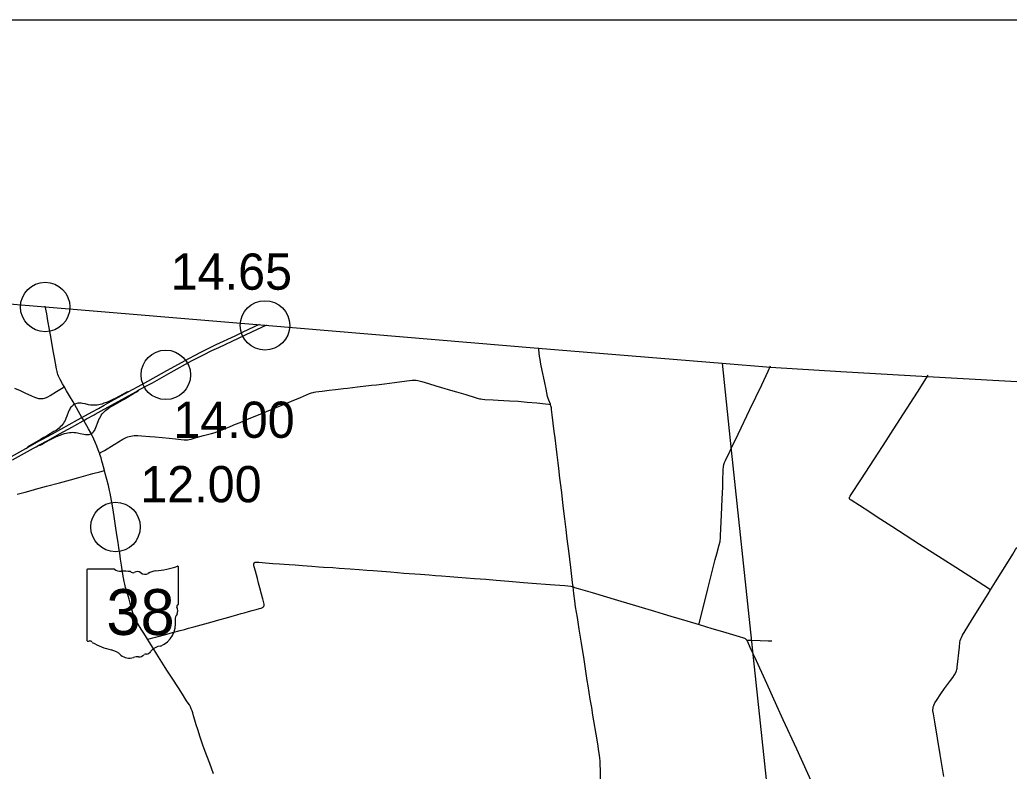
# Model space of a CAD drawing. Extents: x 1597222 to 1925846, y 496284 to 911751.
# Drawn here: x 1697422 to 1727439, y 608558 to 631367 of the extents above; entities that cross this region are included whole.
import ezdxf

# ---------------------------------------------------------------- set-up
doc = ezdxf.new("R2010")
doc.units = 0
for name, color, linetype in [('Default', 7, 'Continuous'), ('GM_X_County', 7, 'Continuous'), ('GM_X_County_Road', 7, 'Continuous'), ('GM_X_Interchange_Ramps', 7, 'Continuous'), ('GM_X_Interstate_Route', 7, 'Continuous'), ('GM_X_State_Route', 7, 'Continuous'), ('GM_X_State_Shield', 7, 'Continuous'), ('GM_X_Township', 7, 'Continuous'), ('GM_X_Township_Road', 7, 'Continuous'), ('SC_Scratch1', 7, 'Continuous')]:
    doc.layers.add(name, color=color, linetype=linetype)

msp = doc.modelspace()

# ---------------------------------------------------------------- linework, layer by layer
at = {"layer": 'Default'}
for centre in [(1698192, 622649), (1698192, 622649), (1704861, 622090), (1704861, 622090), (1704861, 622090), (1701852, 620589), (1701852, 620589), (1700327, 615972), (1700327, 615972)]:
    msp.add_circle(centre, 750, dxfattribs=at)
at = {"layer": 'GM_X_County'}
msp.add_lwpolyline([(1693117, 623083), (1698190, 622658), (1704859, 622098), (1713144, 621404), (1718727, 620944), (1720196, 620823), (1722331, 620688), (1724957, 620538), (1728386, 620349)], dxfattribs=at)
at = {"layer": 'GM_X_County_Road'}
for points in [[(1713520, 619692), (1713518, 619699), (1713468, 619821), (1713452, 619868), (1713435, 619932), (1713389, 620157), (1713340, 620398), (1713274, 620719), (1713233, 620912), (1713208, 621057), (1713194, 621155), (1713171, 621351), (1713162, 621414)], [(1714206, 614155), (1714191, 614282), (1714136, 614738), (1714107, 614999), (1714077, 615243), (1714041, 615536), (1714021, 615699), (1713998, 615895), (1713958, 616220), (1713931, 616448), (1713910, 616627), (1713889, 616807), (1713862, 617018), (1713827, 617311), (1713809, 617458), (1713773, 617751), (1713753, 617914), (1713725, 618158), (1713693, 618419), (1713660, 618679), (1713636, 618874), (1713607, 619119), (1713576, 619379), (1713557, 619542), (1713550, 619590), (1713543, 619622), (1713534, 619653), (1713520, 619692)], [(1697901, 617116), (1698234, 617207), (1698629, 617315), (1698962, 617405), (1699215, 617474), (1699500, 617552), (1699642, 617592), (1699848, 617647), (1699959, 617676), (1699989, 617684)], [(1697347, 616966), (1697585, 617029), (1697838, 617099), (1697901, 617116)], [(1726876, 614063), (1727027, 614309), (1727364, 614853), (1727545, 615146), (1727631, 615285), (1727661, 615324), (1727680, 615344), (1727695, 615358), (1727722, 615376), (1727749, 615388), (1727769, 615396), (1727790, 615402), (1727816, 615409), (1727880, 615419), (1728367, 615486), (1729717, 615669), (1730222, 615734), (1730681, 615801)], [(1701299, 612566), (1701339, 612576), (1701383, 612588), (1701457, 612607), (1701618, 612649), (1701815, 612701), (1702053, 612766), (1702290, 612830), (1702419, 612864), (1702544, 612897), (1702701, 612940), (1702812, 612970), (1703255, 613094), (1703460, 613152), (1703696, 613219), (1703870, 613266), (1704006, 613305), (1704138, 613342), (1704233, 613369), (1704359, 613406), (1704469, 613436), (1704593, 613468), (1704692, 613493), (1704740, 613506), (1704770, 613518), (1704785, 613525), (1704799, 613534), (1704811, 613544), (1704822, 613556), (1704830, 613570), (1704834, 613585), (1704837, 613601), (1704837, 613618), (1704835, 613634), (1704827, 613666), (1704813, 613714), (1704791, 613793), (1704783, 613824), (1704753, 613935), (1704703, 614126), (1704666, 614269), (1704629, 614411), (1704571, 614633), (1704536, 614760), (1704524, 614808), (1704522, 614825), (1704521, 614841), (1704523, 614857), (1704525, 614865), (1704529, 614874), (1704536, 614885), (1704542, 614891), (1704550, 614897), (1704563, 614902), (1704579, 614906), (1704595, 614908), (1704629, 614907), (1704678, 614903), (1704874, 614886), (1705103, 614868), (1705299, 614852), (1705438, 614843), (1705593, 614832), (1705773, 614818), (1706002, 614802), (1706280, 614781), (1706493, 614766), (1706640, 614757), (1706918, 614739), (1707114, 614726), (1707441, 614701), (1707719, 614681), (1707948, 614665), (1708144, 614651), (1708406, 614630), (1708667, 614608), (1708880, 614591), (1709076, 614574), (1709239, 614561), (1709583, 614537), (1709844, 614519), (1710029, 614503), (1710220, 614486), (1710465, 614469), (1710710, 614450), (1711217, 614413), (1711560, 614385), (1711871, 614360), (1712263, 614327), (1712704, 614291), (1713096, 614260), (1713374, 614236), (1713652, 614215), (1713962, 614191), (1714142, 614173), (1714206, 614155)], [(1715040, 608246), (1715036, 608574), (1715032, 608787), (1715028, 608869), (1715021, 608950), (1715009, 609048), (1714991, 609161), (1714954, 609388), (1714907, 609679), (1714839, 610083), (1714811, 610262), (1714774, 610488), (1714731, 610747), (1714666, 611152), (1714640, 611314), (1714541, 611946), (1714461, 612448), (1714393, 612870), (1714338, 613226), (1714285, 613550), (1714259, 613729), (1714229, 613956), (1714206, 614155)], [(1714206, 614155), (1714246, 614138), (1714358, 614107), (1714783, 613982), (1715560, 613748), (1716204, 613555), (1716674, 613416), (1716940, 613336), (1717176, 613265), (1717662, 613120), (1718030, 613009)], [(1725457, 608403), (1725348, 609067), (1725182, 610054), (1725139, 610296), (1725126, 610393), (1725124, 610420), (1725125, 610440), (1725128, 610466), (1725131, 610489), (1725137, 610511), (1725143, 610534), (1725152, 610558), (1725160, 610580), (1725187, 610637), (1725229, 610707), (1725367, 610911), (1725480, 611072), (1725627, 611269), (1725724, 611402), (1725777, 611485), (1725817, 611557), (1725837, 611603), (1725851, 611650), (1725858, 611680), (1725863, 611715), (1725927, 612319), (1725943, 612466), (1725955, 612530), (1725968, 612576), (1725987, 612621), (1726025, 612693), (1726380, 613262), (1726803, 613946), (1726876, 614063)], [(1718030, 613009), (1718414, 612894), (1718743, 612795), (1719242, 612647), (1719380, 612604), (1719405, 612593), (1719424, 612584), (1719439, 612575), (1719450, 612565), (1719460, 612555), (1719471, 612542), (1719475, 612536)], [(1719475, 612536), (1719479, 612529), (1719489, 612510), (1719499, 612491), (1719574, 612327), (1719664, 612128)], [(1719664, 612128), (1719709, 612028), (1720072, 611236), (1720382, 610549), (1720574, 610132), (1720984, 609237), (1721514, 608073), (1722019, 606916), (1722233, 606423), (1722246, 606395), (1722256, 606375), (1722265, 606360), (1722278, 606348), (1722291, 606338), (1722301, 606333)]]:
    msp.add_lwpolyline(points, dxfattribs=at)
at = {"layer": 'GM_X_Interchange_Ramps'}
for points in [[(1700714, 620072), (1700698, 620072), (1700685, 620068), (1700660, 620060), (1700649, 620054), (1700538, 619994), (1700335, 619886), (1700246, 619842), (1700142, 619794), (1700051, 619755), (1699974, 619725), (1699912, 619704), (1699864, 619691), (1699816, 619680), (1699767, 619672), (1699718, 619667), (1699669, 619666), (1699619, 619668), (1699570, 619673), (1699505, 619684), (1699409, 619705), (1699328, 619722), (1699279, 619730), (1699247, 619732), (1699214, 619730), (1699181, 619725), (1699149, 619717), (1699079, 619699)], [(1699588, 618804), (1699610, 618820), (1699636, 618839), (1699648, 618850), (1699659, 618862), (1699680, 618887), (1699697, 618915), (1699712, 618944), (1699732, 618989), (1699799, 619173), (1699824, 619233), (1699846, 619278), (1699869, 619320), (1699895, 619362), (1699924, 619402), (1699956, 619439), (1699989, 619475), (1700025, 619508), (1700063, 619539), (1700103, 619568), (1700158, 619604), (1700256, 619662), (1700587, 619852), (1700875, 620019), (1700969, 620071), (1700992, 620085), (1701011, 620100), (1701024, 620110), (1701032, 620119), (1701038, 620130)], [(1699079, 619699), (1699046, 619673), (1699020, 619652), (1698996, 619630), (1698975, 619605), (1698955, 619579), (1698938, 619551), (1698923, 619522), (1698904, 619477), (1698853, 619339), (1698822, 619263), (1698794, 619204), (1698770, 619161), (1698744, 619119), (1698716, 619080), (1698684, 619042), (1698650, 619007), (1698614, 618974), (1698575, 618943), (1698522, 618905), (1698457, 618866), (1698258, 618748), (1698154, 618687), (1698050, 618628), (1697692, 618424), (1697679, 618414), (1697666, 618400), (1697654, 618384)], [(1698004, 618454), (1698020, 618454), (1698029, 618456), (1698038, 618458), (1698060, 618467), (1698076, 618475), (1698163, 618524), (1698377, 618637), (1698450, 618674), (1698540, 618715), (1698645, 618759), (1698721, 618789), (1698783, 618809), (1698830, 618822), (1698878, 618833), (1698927, 618840), (1698976, 618844), (1699025, 618845), (1699074, 618843), (1699122, 618838), (1699171, 618830), (1699251, 618813), (1699362, 618788), (1699411, 618779), (1699443, 618776), (1699476, 618775), (1699492, 618775), (1699508, 618777), (1699524, 618780), (1699588, 618804)]]:
    msp.add_lwpolyline(points, dxfattribs=at)
at = {"layer": 'GM_X_Interstate_Route'}
for points in [[(1697076, 618065), (1697608, 618358), (1697654, 618384), (1698031, 618593), (1698109, 618637), (1698411, 618803), (1699173, 619222), (1699309, 619297), (1699618, 619468), (1699805, 619571), (1699977, 619666), (1700192, 619786), (1700508, 619960), (1700714, 620072), (1701015, 620240), (1701212, 620349), (1701557, 620540), (1701888, 620722), (1702232, 620911), (1702549, 621085), (1702739, 621185), (1702915, 621276), (1703161, 621399), (1703383, 621506), (1703961, 621778), (1704199, 621891), (1704694, 622125)], [(1702015, 620667), (1702636, 621011), (1702810, 621104), (1703000, 621201), (1703249, 621325), (1703457, 621424), (1704457, 621892), (1704913, 622107)], [(1699704, 619392), (1699893, 619497), (1700941, 620075), (1701038, 620130), (1701444, 620352), (1702015, 620667)], [(1699348, 619195), (1699363, 619203), (1699448, 619251), (1699678, 619378), (1699704, 619392)], [(1697921, 618407), (1698004, 618454), (1698271, 618600), (1698629, 618799), (1699021, 619013)], [(1699021, 619013), (1699090, 619051), (1699348, 619195)], [(1697205, 618011), (1697839, 618362), (1697921, 618407)]]:
    msp.add_lwpolyline(points, dxfattribs=at)
at = {"layer": 'GM_X_State_Route'}
for points in [[(1698770, 620234), (1698720, 620320), (1698647, 620448), (1698617, 620506), (1698598, 620551), (1698580, 620597), (1698566, 620643), (1698555, 620691), (1698539, 620771), (1698478, 621111), (1698448, 621272), (1698405, 621497), (1698372, 621691), (1698322, 621966), (1698277, 622224), (1698239, 622446), (1698195, 622672)], [(1699851, 618174), (1699846, 618191), (1699840, 618209), (1699803, 618316), (1699763, 618423), (1699713, 618545), (1699673, 618635), (1699631, 618724), (1699588, 618804), (1699577, 618826), (1699505, 618955), (1699363, 619203), (1699334, 619254), (1699309, 619297), (1699203, 619481), (1699079, 619699), (1699041, 619766), (1698934, 619951), (1698843, 620107), (1698770, 620234)], [(1699931, 617905), (1699913, 617972), (1699886, 618066), (1699851, 618174)], [(1703297, 608484), (1703183, 608792), (1703098, 609023), (1702990, 609315), (1702934, 609469), (1702892, 609593), (1702820, 609828), (1702776, 609970), (1702733, 610111), (1702697, 610237), (1702669, 610329), (1702649, 610393), (1702624, 610456), (1702598, 610513), (1702568, 610572), (1702531, 610628), (1702484, 610697), (1702386, 610849), (1702253, 611056), (1702022, 611414), (1701906, 611593), (1701836, 611704), (1701732, 611871), (1701584, 612108), (1701471, 612289), (1701351, 612484), (1701299, 612566), (1701263, 612622), (1701186, 612748), (1701107, 612873), (1700995, 613055), (1700954, 613125), (1700924, 613183), (1700904, 613228), (1700887, 613274), (1700856, 613367), (1700782, 613619), (1700738, 613777), (1700705, 613887), (1700665, 614012), (1700630, 614138), (1700606, 614233), (1700590, 614313), (1700551, 614540), (1700510, 614815), (1700482, 614994), (1700456, 615172), (1700430, 615334), (1700404, 615496), (1700379, 615675), (1700340, 615934), (1700285, 616291), (1700245, 616550), (1700206, 616777), (1700164, 617003), (1700146, 617083), (1700109, 617226), (1700014, 617591), (1699989, 617684), (1699931, 617905)]]:
    msp.add_lwpolyline(points, dxfattribs=at)
at = {"layer": 'GM_X_State_Shield'}
for p, q in [((1699453, 614658), (1699453, 612545)), ((1700296, 614695), (1699481, 614695)), ((1702237, 613641), (1702237, 614747)), ((1702237, 613642), (1702237, 613641))]:
    msp.add_line(p, q, dxfattribs=at)
for centre, radius, start, end in [((1701246, 617576), 2953, 275.8445, 288.9065), ((1702207, 614752), 31, 351.8621, 97.738), ((1699485, 614663), 32.3, 98.1301, 188.1301), ((1700490, 614940), 313, 231.6195, 271.1119), ((1700594, 613508), 1123, 80.4867, 94.9883), ((1700849, 614674), 90.3, 219.7921, 297.1024), ((1700981, 614429), 188, 54.4667, 119.1411), ((1701224, 614764), 226, 233.8562, 294.8282), ((1701622, 614049), 594, 97.3462, 120.7689), ((1702230, 613560), 48, 107.944, 210.337), ((1702204, 613637), 33.2, 289.6038, 7.7341), ((1702349, 613179), 210, 136.8065, 186.9296), ((1701925, 613421), 288, 340.033, 23.6496), ((1701411, 613038), 739, 292.3089, 8.9858), ((1699485, 612540), 32.5, 171.9584, 258.3066), ((1699490, 612757), 248, 267.339, 280.6039), ((1699541, 612423), 89.5, 29.7484, 93.2717), ((1700672, 614322), 2132, 240.4129, 257.1985), ((1701722, 611952), 404, 94.4031, 142.5768), ((1700036, 611596), 667, 47.1842, 75.836), ((1700757, 612413), 423, 230.7004, 286.2918), ((1701033, 612254), 226, 268.777, 315.5493), ((1701237, 612050), 63.5, 65.7517, 132.6484), ((1701210, 612340), 239, 282.8732, 323.2771), ((1701002, 611682), 348, 85.6951, 111.2099)]:
    msp.add_arc(centre, radius, start, end, dxfattribs=at)
at = {"layer": 'GM_X_Township'}
msp.add_lwpolyline([(1718727, 620944), (1719007, 618308), (1719624, 612493), (1719675, 612012), (1720412, 605075), (1720984, 599696), (1721634, 593580), (1721696, 592990)], dxfattribs=at)
at = {"layer": 'GM_X_Township_Road'}
for points in [[(1719006, 618352), (1719216, 618793), (1719569, 619534), (1719930, 620286), (1720126, 620705), (1720198, 620859)], [(1722649, 616960), (1722942, 617405), (1723351, 618036), (1723706, 618587), (1723916, 618917), (1724653, 620061), (1724983, 620576)], [(1697266, 620187), (1697430, 620111), (1697595, 620038), (1697759, 619962), (1697781, 619952)], [(1697781, 619952), (1697864, 619914), (1697925, 619890), (1697956, 619881), (1697988, 619874), (1698037, 619869), (1698070, 619868), (1698103, 619869), (1698135, 619873), (1698168, 619880), (1698199, 619890), (1698229, 619903), (1698273, 619924), (1698345, 619965), (1698540, 620087), (1698734, 620210), (1698770, 620234)], [(1699840, 618209), (1699875, 618230), (1699987, 618297), (1700283, 618473), (1700551, 618633), (1700608, 618665), (1700653, 618686), (1700699, 618704), (1700745, 618720), (1700793, 618732), (1700841, 618741), (1700890, 618746), (1700939, 618748), (1701005, 618747), (1701119, 618739), (1701364, 618718), (1701527, 618703), (1701740, 618683), (1701952, 618664), (1702148, 618644), (1702409, 618619), (1702458, 618616), (1702491, 618616), (1702523, 618619), (1702556, 618625), (1702619, 618641), (1702777, 618684), (1702999, 618745), (1703236, 618810), (1703346, 618842), (1703424, 618868), (1703516, 618904), (1703804, 619022), (1703971, 619089), (1704107, 619147), (1704334, 619241), (1704562, 619334), (1705077, 619547), (1705319, 619648), (1705456, 619704), (1705667, 619793), (1705940, 619906), (1706212, 620020), (1706274, 620043), (1706320, 620058), (1706352, 620066), (1706401, 620074), (1706498, 620085), (1706596, 620096), (1706808, 620121), (1707003, 620144), (1707247, 620175), (1707361, 620189), (1707670, 620225), (1708094, 620273), (1708240, 620290), (1708484, 620320), (1708793, 620359), (1709168, 620404), (1709331, 620425), (1709380, 620429), (1709412, 620429), (1709445, 620428), (1709494, 620422), (1709542, 620411), (1709620, 620387), (1709824, 620324), (1710044, 620258), (1710217, 620207), (1710484, 620128), (1710673, 620074), (1710815, 620032), (1710956, 619988), (1711237, 619899), (1711300, 619881), (1711364, 619866), (1711412, 619858), (1711461, 619851), (1711526, 619846), (1711788, 619832), (1711936, 619824), (1712279, 619805), (1712541, 619788), (1712819, 619765), (1713113, 619735), (1713373, 619707), (1713471, 619697), (1713520, 619692)], [(1718030, 613009), (1718035, 613030), (1718169, 613568), (1718247, 613887), (1718300, 614093), (1718390, 614459), (1718523, 614984), (1718568, 615159), (1718638, 615429), (1718667, 615536), (1718674, 615569), (1718680, 615611), (1718685, 615702), (1718712, 616341), (1718734, 616818), (1718746, 617192), (1718754, 617400), (1718764, 617664), (1718766, 617736), (1718770, 617780), (1718774, 617825), (1718779, 617850), (1718785, 617871), (1718793, 617897), (1718805, 617929), (1718835, 617991), (1718877, 618078), (1718934, 618197), (1719006, 618352)], [(1726876, 614063), (1726856, 614076), (1726842, 614085), (1726496, 614304), (1725819, 614737), (1725403, 615001), (1724714, 615445), (1724081, 615856), (1723874, 615990), (1723434, 616274), (1723214, 616418), (1722898, 616624), (1722649, 616782), (1722624, 616798), (1722615, 616805), (1722609, 616810), (1722605, 616815), (1722601, 616821), (1722597, 616830), (1722595, 616837), (1722593, 616845), (1722592, 616853), (1722592, 616857), (1722593, 616861), (1722593, 616865), (1722594, 616869), (1722595, 616872), (1722597, 616877), (1722598, 616880), (1722600, 616884), (1722602, 616888), (1722617, 616912), (1722649, 616960)], [(1719475, 612536), (1719501, 612535), (1719599, 612534), (1719624, 612533)], [(1719624, 612533), (1719879, 612525), (1720126, 612517), (1720242, 612514)]]:
    msp.add_lwpolyline(points, dxfattribs=at)
at = {"layer": 'SC_Scratch1'}
msp.add_lwpolyline([(1597222, 631367), (1793472, 631367), (1793472, 496867), (1597222, 496867)], close=True, dxfattribs=at)

# ---------------------------------------------------------------- texts
at = {"layer": 'Default'}
for s, p in [('14.65', (1702000, 623173)), ('14.65', (1702000, 623173)), ('14.00', (1702080, 618677)), ('14.00', (1702080, 618677)), ('12.00', (1701077, 616722)), ('12.00', (1701077, 616722))]:
    msp.add_text(s, height=1100, dxfattribs=at).set_placement(p)
at = {"layer": 'GM_X_State_Shield'}
msp.add_text('38', height=1392.2, dxfattribs=at).set_placement((1700049, 612694))

doc.saveas('drawing.dxf')
